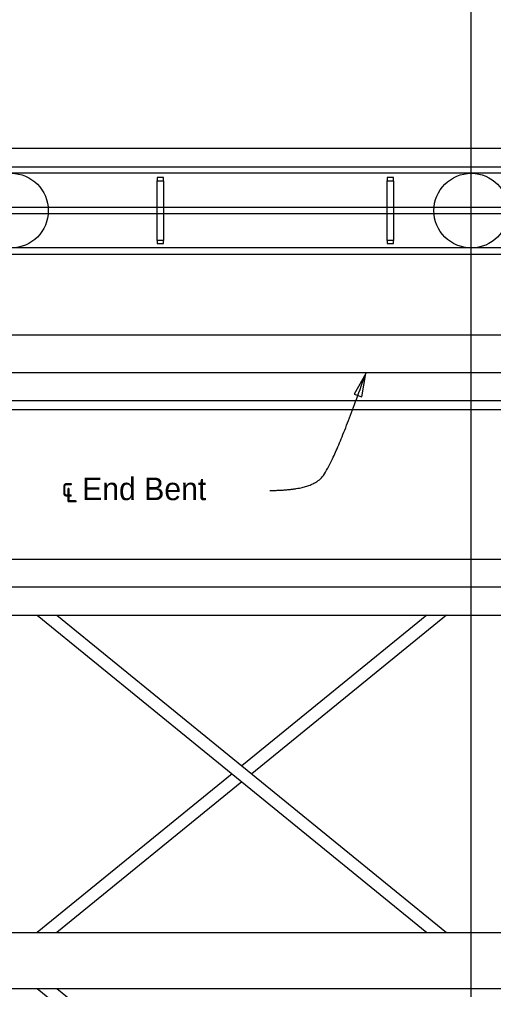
# Model space of a CAD drawing. Extents: x 10618 to 10724, y 76431 to 76484.
# Drawn here: x 10642.71 to 10649.06, y 76464.3 to 76477.29 of the extents above; entities that cross this region are included whole.
import ezdxf

# ---------------------------------------------------------------- set-up
doc = ezdxf.new("R2010")
doc.units = 0
for name, color, linetype in [('CL_Minor', 7, 'Continuous'), ('Dimension', 7, 'Continuous'), ('SteelMisc', 7, 'Continuous'), ('SteelMisc_h', 7, 'Continuous'), ('TextStructures', 7, 'Continuous'), ('Wood_h', 7, 'Continuous')]:
    doc.layers.add(name, color=color, linetype=linetype)

msp = doc.modelspace()

# ---------------------------------------------------------------- linework, layer by layer
at = {"layer": 'CL_Minor'}
for points in [[(10648.764, 76452.345), (10648.764, 76478.808), (10648.764, 76483.56)], [(10632.005, 76472.56), (10665.499, 76472.56)], [(10633.601, 76472.185), (10663.013, 76472.185), (10663.926, 76472.185)]]:
    msp.add_lwpolyline(points, dxfattribs=at)
at = {"layer": 'Dimension'}
msp.add_lwpolyline([(10647.351, 76472.548), (10647.197, 76472.27), (10647.297, 76472.235)], close=True, dxfattribs=at)
msp.add_open_spline([(10646.065, 76470.98), (10646.585, 76470.98), (10646.911, 76471.297), (10647.351, 76472.548)], degree=2, dxfattribs=at)
at = {"layer": 'SteelMisc'}
for p, q in [((10648.764, 76474.144), (10648.764, 76475.311)), ((10660.764, 76474.769), (10636.764, 76474.769)), ((10660.764, 76474.685), (10636.764, 76474.685)), ((10660.764, 76469.686), (10636.764, 76469.686))]:
    msp.add_line(p, q, dxfattribs=at)
at = {"layer": 'SteelMisc_h'}
for p, q in [((10636.305, 76470.061), (10661.222, 76470.061)), ((10636.305, 76469.311), (10661.222, 76469.311)), ((10642.947, 76469.311), (10648.171, 76465.061)), ((10643.211, 76469.311), (10648.435, 76465.061)), ((10648.171, 76469.311), (10645.691, 76467.293)), ((10648.435, 76469.311), (10645.823, 76467.186)), ((10645.559, 76467.186), (10642.947, 76465.061)), ((10645.691, 76467.078), (10643.211, 76465.061)), ((10636.305, 76465.061), (10661.222, 76465.061)), ((10636.305, 76464.311), (10661.222, 76464.311)), ((10642.947, 76464.311), (10648.171, 76460.061)), ((10643.211, 76464.311), (10648.435, 76460.061))]:
    msp.add_line(p, q, dxfattribs=at)
for points in [[(10660.62, 76475.311), (10636.904, 76475.311)], [(10636.764, 76474.144), (10660.764, 76474.144)]]:
    msp.add_lwpolyline(points, dxfattribs=at)
for points in [[(10644.639, 76475.128), (10644.639, 76475.17), (10644.555, 76475.17), (10644.555, 76475.128)], [(10644.555, 76474.326), (10644.555, 76475.128), (10644.639, 76475.128), (10644.639, 76474.326)], [(10647.722, 76475.128), (10647.722, 76475.17), (10647.639, 76475.17), (10647.639, 76475.128)], [(10647.639, 76474.326), (10647.639, 76475.128), (10647.722, 76475.128), (10647.722, 76474.326)], [(10644.639, 76474.285), (10644.639, 76474.326), (10644.555, 76474.326), (10644.555, 76474.285)], [(10647.722, 76474.285), (10647.722, 76474.326), (10647.639, 76474.326), (10647.639, 76474.285)]]:
    msp.add_lwpolyline(points, close=True, dxfattribs=at)
at = {"layer": 'Wood_h'}
for p, q in [((10663.855, 76475.561), (10633.277, 76475.561)), ((10662.639, 76475.227), (10634.926, 76475.227)), ((10662.663, 76474.227), (10634.926, 76474.227)), ((10660.568, 76473.06), (10636.927, 76473.06)), ((10660.568, 76472.06), (10636.927, 76472.06))]:
    msp.add_line(p, q, dxfattribs=at)
for centre in [(10642.597, 76474.727), (10648.764, 76474.727)]:
    msp.add_circle(centre, 0.5, dxfattribs=at)

# ---------------------------------------------------------------- texts
at = {"layer": 'TextStructures'}
msp.add_text('℄ End Bent', height=0.3024, dxfattribs=at).set_placement((10643.274, 76470.85))

doc.saveas('drawing.dxf')
